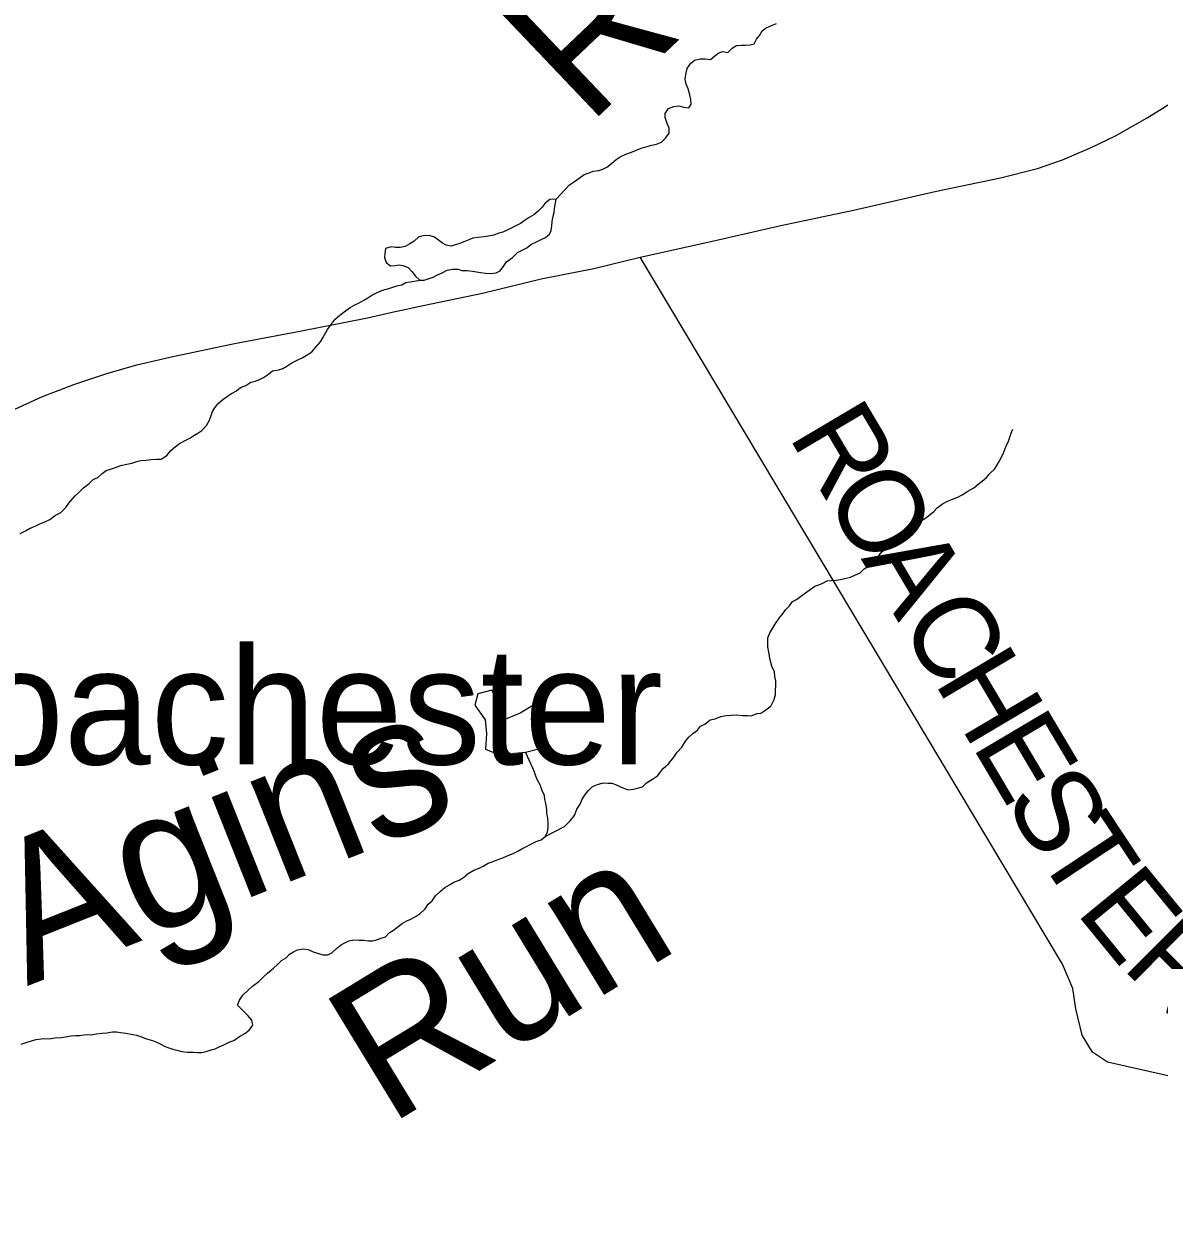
# Model space of a CAD drawing. Extents: x 1310247 to 1664935, y 284496 to 704931.
# Drawn here: x 1517876 to 1521928, y 495651 to 499915 of the extents above; entities that cross this region are included whole.
import ezdxf

# ---------------------------------------------------------------- set-up
doc = ezdxf.new("R2010")
doc.units = 0
for name, color, linetype in [('GM_P_State_Shield', 7, 'Continuous'), ('GM_X_County_Road_Text', 7, 'Continuous'), ('GM_X_Interstate_Route', 7, 'Continuous'), ('GM_X_Minor_Lake_Text', 7, 'Continuous'), ('GM_X_Minor_River', 7, 'Continuous'), ('GM_X_Minor_River_Text', 7, 'Continuous'), ('GM_X_Township_Road', 7, 'Continuous')]:
    doc.layers.add(name, color=color, linetype=linetype)

msp = doc.modelspace()

# ---------------------------------------------------------------- linework, layer by layer
at = {"layer": 'GM_P_State_Shield'}
for points in [[(1519190.8, 498885), (1519300.4, 498909.6), (1519513.2, 498953.9), (1519722.1, 499004.2), (1519910.4, 499041), (1520075.7, 499081.7), (1520328, 499137.7), (1520577.4, 499194.9), (1520836.7, 499249.8), (1521132.7, 499317.8), (1521361.7, 499365.5), (1521493.5, 499398), (1521583, 499429.5), (1521684.9, 499472.9), (1521772.7, 499514.6), (1521885.3, 499579.6), (1522055.5, 499685.2)], [(1517827.5, 498531.5), (1517941.8, 498584.5), (1518053.8, 498627.6), (1518171.7, 498666.4), (1518279.4, 498697.5), (1518396.9, 498724.3), (1518628, 498774), (1518860.8, 498817.6), (1519101.8, 498865), (1519190.8, 498885)]]:
    msp.add_lwpolyline(points, dxfattribs=at)
at = {"layer": 'GM_X_County_Road_Text'}
msp.add_lwpolyline([(1523106.7, 496046.9), (1523055.5, 496055.6), (1523013.1, 496042.2), (1522959.5, 495958.8), (1522841.5, 495734), (1522802.5, 495682.5), (1522769.9, 495650.9), (1522713.7, 495655.8), (1522638.3, 495717.1), (1522281.8, 496037.5), (1522038.4, 496141.5), (1521744.1, 496208.2), (1521690.5, 496243.2), (1521653.3, 496303.9), (1521630.6, 496398.5), (1521619.7, 496470.9), (1521582.9, 496557.7), (1520075.7, 499081.7)], dxfattribs=at)
at = {"layer": 'GM_X_Minor_River'}
for points in [[(1519775.2, 499289.3), (1519753, 499287.8), (1519736.6, 499274.2), (1519726.2, 499260.4), (1519711.8, 499246.7), (1519695.4, 499233), (1519679.1, 499223.4), (1519664.8, 499213.7), (1519648.5, 499202.1), (1519617.9, 499186.8), (1519603.7, 499179.1), (1519585.4, 499171.5), (1519571.2, 499167.8), (1519553, 499160.2), (1519532.8, 499156.7), (1519518.7, 499155), (1519496.5, 499151.6), (1519478.4, 499150), (1519464.2, 499144.3), (1519445.9, 499136.7), (1519431.7, 499131), (1519415.5, 499125.4), (1519401.3, 499121.8), (1519383.3, 499124.2), (1519369.5, 499132.5), (1519355.7, 499142.9), (1519341.9, 499153.3), (1519321.9, 499159.8), (1519301.8, 499158.3), (1519285.7, 499154.6), (1519269.2, 499139), (1519252.9, 499129.3), (1519236.6, 499119.7), (1519218.4, 499116.1), (1519202.3, 499116.5), (1519186.3, 499118.9), (1519166.1, 499113.4), (1519163.6, 499095.4), (1519163.3, 499081.3), (1519168.9, 499063.2), (1519184.6, 499050.7), (1519200.7, 499052.4), (1519214.8, 499054), (1519228.8, 499051.7), (1519246.8, 499045.2), (1519260.5, 499030.9), (1519274.1, 499014.5), (1519288.3, 499001.4)], [(1519288.3, 499001.4), (1519289.8, 499000), (1519303.9, 498999.7), (1519322.1, 499005.3), (1519336.3, 499011), (1519352.6, 499018.6), (1519368.8, 499026.2), (1519387.1, 499035.8), (1519405.3, 499039.4), (1519425.4, 499038.9), (1519439.3, 499034.6), (1519457.4, 499034.1), (1519477.4, 499031.6), (1519491.4, 499029.3), (1519505.4, 499027), (1519523.5, 499024.5), (1519541.5, 499024.1), (1519561.7, 499025.6), (1519575.9, 499033.3), (1519588.4, 499051), (1519598.8, 499064.8), (1519619.3, 499080.4), (1519637.8, 499098), (1519652.1, 499105.7), (1519670.4, 499115.3), (1519684.7, 499127), (1519705.1, 499136.5), (1519719.3, 499144.2), (1519737.6, 499151.8), (1519751.9, 499163.5), (1519758.3, 499177.3), (1519760.7, 499193.3), (1519761.1, 499209.4), (1519763.5, 499223.4), (1519768, 499241.3), (1519770.3, 499255.3), (1519775.2, 499289.3)], [(1519666.8, 497314.3), (1519717.4, 497327.3), (1519736.6, 497379.1), (1519711.5, 497433.9), (1519698.5, 497484.3), (1519647.5, 497453.3), (1519594.7, 497432.3), (1519573.7, 497484.9), (1519546.5, 497535.7), (1519495.9, 497522.7), (1519485, 497482.8)], [(1519485, 497482.8), (1519522.2, 497429.8), (1519527.2, 497379.5), (1519524, 497325.3), (1519575.9, 497304.2), (1519626.4, 497311.2), (1519666.8, 497314.3)]]:
    msp.add_lwpolyline(points, dxfattribs=at)
at = {"layer": 'GM_X_Minor_River_Text'}
for points in [[(1519775.2, 499289.3), (1519822.7, 499340.3), (1519841, 499351.9), (1519857.4, 499363.5), (1519875.8, 499377.1), (1519894, 499382.7), (1519908.2, 499388.4), (1519928.4, 499391.9), (1519942.6, 499395.6), (1519956.8, 499403.3), (1519973.3, 499416.9), (1519989.7, 499430.6), (1520004, 499440.3), (1520024.3, 499449.8), (1520044.6, 499457.3), (1520058.8, 499463), (1520079.1, 499470.6), (1520095.3, 499476.2), (1520117.5, 499481.7), (1520133.7, 499485.3), (1520151.9, 499492.9), (1520166.3, 499506.6), (1520178.8, 499524.3), (1520179.3, 499542.4), (1520171.7, 499558.6), (1520164.2, 499580.9), (1520164.5, 499594.9), (1520177, 499612.6), (1520195.3, 499620.2), (1520213.4, 499621.8), (1520231.4, 499617.4), (1520249.4, 499614.9), (1520257.8, 499628.8), (1520256.2, 499644.8), (1520252.6, 499661), (1520247.1, 499683.2), (1520239.5, 499699.4), (1520235.9, 499717.6), (1520238.3, 499733.6), (1520242.9, 499755.5), (1520255.4, 499773.3), (1520269.7, 499785), (1520290, 499790.5), (1520308, 499790.1), (1520326.1, 499787.6), (1520342.5, 499801.3), (1520356.8, 499811), (1520371, 499816.6), (1520389, 499812.2), (1520403.4, 499827.9), (1520419.7, 499837.5), (1520437.8, 499839.1), (1520451.9, 499838.8), (1520468, 499840.4), (1520482.2, 499844), (1520490.6, 499859.9), (1520501, 499873.7), (1520511.4, 499889.5), (1520525.8, 499901.2), (1520544, 499908.8), (1520562.3, 499916.3)], [(1518538, 498500.5), (1518544.5, 498516.5), (1518548.8, 498530.4), (1518557.2, 498544.2), (1518567.6, 498558), (1518586.1, 498573.6), (1518602.4, 498585.3), (1518616.7, 498595), (1518635, 498604.5), (1518649.4, 498616.2), (1518667.7, 498623.8), (1518686, 498635.4), (1518702.2, 498639), (1518716.4, 498644.7), (1518730.7, 498652.4), (1518749, 498664), (1518763.4, 498675.7), (1518785.6, 498679.2), (1518799.8, 498684.8), (1518814, 498692.5), (1518832.4, 498704.1), (1518850.7, 498713.7), (1518871.1, 498723.2), (1518889.4, 498734.8), (1518903.7, 498744.5), (1518918.2, 498760.2), (1518934.8, 498779.9), (1518943.1, 498793.7), (1518959.9, 498823.4), (1518972.4, 498841.2), (1518987, 498860.9), (1519003.4, 498874.5), (1519023.9, 498890.1), (1519040.3, 498901.7), (1519056.6, 498911.4), (1519072.8, 498919), (1519089.2, 498928.6), (1519103.4, 498936.3), (1519117.7, 498946), (1519132, 498953.7), (1519150.2, 498961.3), (1519164.4, 498967), (1519178.6, 498970.6), (1519192.7, 498974.3), (1519207, 498980), (1519225.1, 498983.6), (1519239.4, 498991.2), (1519261.6, 498994.7), (1519289.8, 499000)], [(1517862.9, 498095.5), (1517881.3, 498105.1), (1517895.5, 498112.8), (1517917.9, 498122.3), (1517932.1, 498130), (1517948.3, 498135.6), (1517968.6, 498145.1), (1517989.1, 498160.7), (1518007.4, 498170.3), (1518026, 498187.9), (1518036.4, 498203.7), (1518059.1, 498229.2), (1518073.5, 498242.9), (1518088, 498258.6), (1518108.5, 498274.2), (1518122.9, 498287.9), (1518139.1, 498295.5), (1518155.6, 498309.1), (1518169.9, 498320.8), (1518188.1, 498326.4), (1518206.4, 498332), (1518220.6, 498337.7), (1518242.8, 498343.1), (1518261, 498346.7), (1518279.2, 498352.3), (1518293.3, 498356), (1518311.5, 498357.5), (1518329.6, 498359.1), (1518349.7, 498360.6), (1518365.8, 498360.2), (1518386.2, 498373.8), (1518400.7, 498391.5), (1518415.1, 498405.2), (1518431.5, 498416.8), (1518453.9, 498428.3), (1518468.1, 498436), (1518482.4, 498445.7), (1518496.7, 498453.4), (1518511, 498463.1), (1518527.5, 498480.7), (1518538, 498500.5)], [(1521172.5, 498210.3), (1521190.8, 498217.9), (1521209, 498225.5), (1521225.3, 498233.1), (1521245.7, 498246.7), (1521266.1, 498258.2), (1521282.5, 498271.9), (1521296.8, 498281.6), (1521311.2, 498295.3), (1521323.6, 498309), (1521340.1, 498324.7), (1521348.5, 498338.5), (1521356.9, 498352.4), (1521367.4, 498372.2), (1521373.8, 498386.1), (1521382.4, 498407.9), (1521388.7, 498421.8), (1521395.2, 498439.7), (1521399.6, 498453.6), (1521405.9, 498467.5)], [(1519736.3, 497013.1), (1519805.5, 497049.5), (1519826.1, 497069.1), (1519840.6, 497088.8), (1519849.2, 497110.7), (1519861.7, 497128.4), (1519868.2, 497146.3), (1519880.7, 497164.1), (1519891.1, 497177.9), (1519905.5, 497191.6), (1519923.7, 497199.2), (1519944, 497204.7), (1519960, 497204.3), (1519974.1, 497204), (1519988, 497199.6), (1520005.9, 497191.2), (1520019.8, 497184.8), (1520033.8, 497180.5), (1520051.9, 497182), (1520066, 497185.7), (1520084.3, 497191.3), (1520098.7, 497205), (1520123.1, 497220.4), (1520137.5, 497230.1), (1520158.2, 497255.7), (1520176.7, 497273.3), (1520195.4, 497297), (1520207.9, 497314.7), (1520224.4, 497332.4), (1520237, 497354.1), (1520249.4, 497367.9), (1520263.8, 497381.6), (1520280.2, 497393.2), (1520290.5, 497407), (1520306.8, 497414.6), (1520325.3, 497430.2), (1520343.4, 497433.8), (1520363.7, 497441.4), (1520381.9, 497444.9), (1520400, 497446.5), (1520418.1, 497448.1), (1520440.2, 497445.5), (1520458.2, 497445.1), (1520472.3, 497444.8), (1520492.6, 497452.3), (1520506.7, 497454), (1520521, 497463.6), (1520541.5, 497479.2), (1520554.1, 497503), (1520558.6, 497520.9), (1520558.9, 497535), (1520559.4, 497553), (1520559.8, 497569), (1520556.2, 497585.2), (1520554.6, 497601.3), (1520545, 497621.6), (1520539.6, 497643.8), (1520534.2, 497672), (1520530.7, 497690.1), (1520531, 497704.2), (1520531.5, 497722.2), (1520538, 497740.1), (1520546.3, 497754), (1520558.9, 497773.7), (1520571.4, 497793.5), (1520583.8, 497807.2), (1520594.3, 497823), (1520608.7, 497836.7), (1520619.1, 497852.5), (1520633.4, 497860.2), (1520666.1, 497883.5), (1520682.5, 497895.1), (1520698.8, 497906.8), (1520713, 497912.5), (1520727.2, 497918.1), (1520743.5, 497925.8), (1520757.6, 497927.4), (1520775.7, 497929), (1520789.8, 497930.7), (1520806, 497934.3), (1520826.2, 497939.8), (1520844.5, 497947.4), (1520860.7, 497955), (1520875.1, 497968.7), (1520893.5, 497980.3), (1520912.2, 498004), (1520928.6, 498017.6), (1520939, 498031.4), (1520961.5, 498046.9), (1520977.8, 498058.5), (1520998.3, 498072.1), (1521010.7, 498085.8), (1521024.9, 498093.5), (1521043.4, 498107.1), (1521067.9, 498126.6), (1521084.5, 498144.2), (1521104.9, 498157.8), (1521123.4, 498173.4), (1521135.8, 498187.2), (1521154.2, 498200.8), (1521172.5, 498210.3)], [(1518657.4, 496447.2), (1518675.9, 496464.8), (1518692.3, 496478.5), (1518714.8, 496496), (1518729.2, 496509.7), (1518745.7, 496525.4), (1518766.2, 496542.9), (1518780.6, 496556.6), (1518795, 496570.3), (1518811.4, 496580), (1518823.7, 496593.7), (1518838, 496601.4), (1518852.3, 496609.1), (1518872.4, 496612.6), (1518890.5, 496610.1), (1518908.3, 496601.7), (1518924.3, 496597.3), (1518942.2, 496590.8), (1518960.3, 496590.4), (1518974.5, 496598.1), (1518991, 496613.8), (1519009.4, 496627.3), (1519035.9, 496640.8), (1519054, 496644.3), (1519072.1, 496643.9), (1519088.2, 496643.5), (1519106.2, 496641.1), (1519120.2, 496640.7), (1519134.4, 496644.4), (1519150.6, 496650), (1519166.8, 496655.6), (1519179.2, 496669.4), (1519195.5, 496679), (1519211.9, 496692.7), (1519226.2, 496702.4), (1519242.6, 496712), (1519256.8, 496717.7), (1519273.1, 496727.3), (1519289.4, 496737), (1519307.9, 496754.6), (1519318.4, 496772.4), (1519332.8, 496784.1), (1519345.3, 496801.8), (1519361.7, 496817.5), (1519378.1, 496831.1), (1519394.4, 496840.8), (1519410.8, 496850.4), (1519429, 496858), (1519445.3, 496867.6), (1519461.7, 496881.3), (1519482.1, 496892.8), (1519500.4, 496900.4), (1519514.7, 496908.1), (1519533, 496917.7), (1519547.2, 496923.3), (1519561.4, 496929), (1519581.7, 496936.6), (1519595.9, 496942.2), (1519610.1, 496947.9), (1519624.3, 496953.6), (1519638.5, 496961.3), (1519652.8, 496969), (1519667, 496976.6), (1519685.4, 496986.2), (1519703.7, 496995.8), (1519721.9, 497001.4), (1519736.3, 497013.1), (1519744.7, 497028.9), (1519747.2, 497046.9), (1519747.6, 497063), (1519745.9, 497079.1), (1519742.4, 497097.2), (1519742.7, 497111.2), (1519739.2, 497131.4), (1519735.6, 497145.5), (1519733.9, 497159.6), (1519724.4, 497179.9), (1519718.8, 497198.1), (1519709.2, 497214.4), (1519703.5, 497228.5), (1519697.8, 497242.7), (1519692.1, 497256.9), (1519686.5, 497271.1), (1519666.8, 497314.3)], [(1517865.5, 496271.7), (1517887.8, 496279.2), (1517906, 496284.8), (1517920.1, 496288.5), (1517946.3, 496291.8), (1517966.4, 496291.3), (1517986.6, 496294.9), (1518008.7, 496296.3), (1518024.8, 496298), (1518045, 496301.5), (1518061.1, 496303.1), (1518075.2, 496302.8), (1518097.4, 496306.2), (1518115.4, 496305.8), (1518133.6, 496309.4), (1518153.7, 496310.9), (1518171.8, 496312.5), (1518192, 496316), (1518206.1, 496315.7), (1518220.1, 496313.3), (1518240.1, 496310.8), (1518264.1, 496306.2), (1518278.1, 496303.9), (1518292.1, 496299.5), (1518313.9, 496291), (1518337.9, 496284.4), (1518359.7, 496273.8), (1518379.5, 496263.3), (1518393.5, 496259), (1518407.5, 496254.6), (1518421.4, 496250.3), (1518439.4, 496245.8), (1518459.4, 496243.3), (1518479.5, 496242.9), (1518495.5, 496242.5), (1518509.6, 496242.1), (1518525.8, 496245.8), (1518544, 496251.3), (1518558.1, 496255), (1518572.4, 496262.7), (1518586.6, 496268.4), (1518611, 496279.8), (1518625.2, 496285.5), (1518645.6, 496299.1), (1518664, 496310.6), (1518680.3, 496322.3), (1518692.8, 496340), (1518689.3, 496358.2), (1518675.6, 496374.6), (1518656, 496393.1), (1518638.4, 496411.6), (1518644.9, 496429.5), (1518657.4, 496447.2)]]:
    msp.add_lwpolyline(points, dxfattribs=at)

# ---------------------------------------------------------------- texts
at = {"layer": 'GM_X_Interstate_Route'}
msp.add_text('Roachester', height=417, rotation=0, dxfattribs=at).set_placement((1517305.7, 497270.8))
at = {"layer": 'GM_X_Minor_Lake_Text'}
for s, height, rotation, p in [('Run', 500, 43.5704, (1519888.3, 499547.8)), ('Agins', 500, 21.6815, (1517886.6, 496478.6)), ('Run', 500.01, 31.3682, (1519177.3, 495978.8))]:
    msp.add_text(s, height=height, rotation=rotation, dxfattribs=at).set_placement(p)
at = {"layer": 'GM_X_Township_Road'}
for s, rotation, p in [('R', 300.6432, (1520602.1, 498444.6)), ('O', 300.6432, (1520727.7, 498232.6)), ('A', 300.6432, (1520862.3, 498005.5)), ('C', 300.6432, (1520996.8, 497778.4)), ('H', 300.6432, (1521122.4, 497566.4)), ('E', 300.6432, (1521257, 497339.3)), ('S', 300.6432, (1521371.4, 497146.2)), ('T', 303.5384, (1521483.3, 496958.1)), ('E', 309.3288, (1521627, 496744.4)), ('R', 315.1191, (1521791.4, 496546.3))]:
    msp.add_text(s, height=300, rotation=rotation, dxfattribs=at).set_placement(p)

doc.saveas('drawing.dxf')
